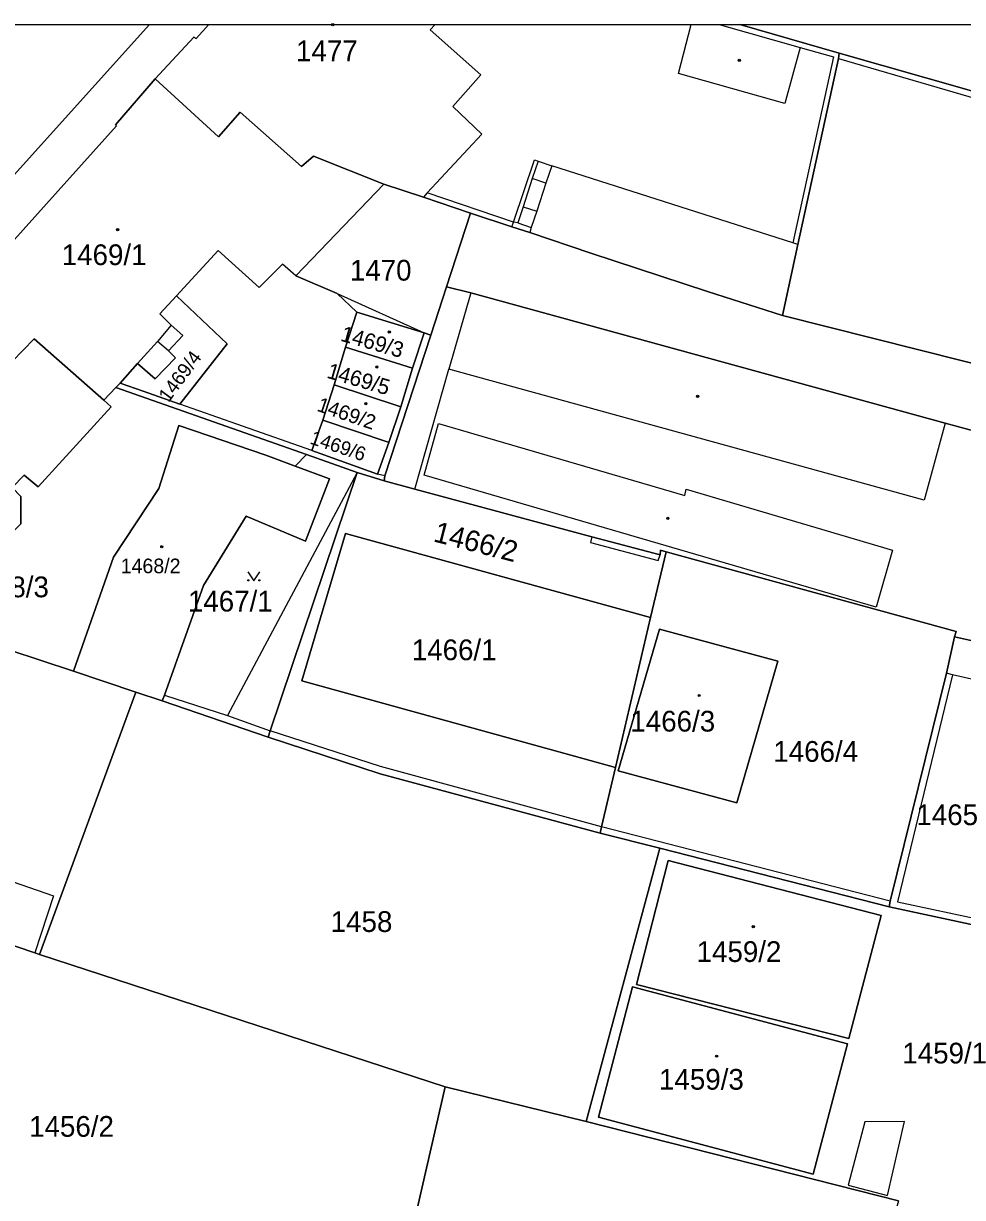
# Model space of a CAD drawing. Extents: x -598934 to -598196, y -1162208 to -1161502.
# Drawn here: x -598625.4 to -598548.4, y -1161601.3 to -1161505.1 of the extents above; entities that cross this region are included whole.
import ezdxf

# ---------------------------------------------------------------- set-up
doc = ezdxf.new("R2010")
doc.units = 0
for name, color, linetype in [('KN_CAR_KR', 7, 'Continuous'), ('KN_KULTURY', 7, 'Continuous'), ('KN_PARC_CIS_POZ', 7, 'Continuous'), ('KN_PARC_CIS_STAV', 7, 'Continuous'), ('KN_PARC_PLOCHA', 7, 'Continuous'), ('parcely_l', 7, 'Continuous')]:
    doc.layers.add(name, color=color, linetype=linetype)

msp = doc.modelspace()

# ---------------------------------------------------------------- linework, layer by layer
at = {"layer": 'KN_CAR_KR'}
for points in [[(-598694.17, -1161593.02), (-598615.083, -1161505.182)], [(-598591.66, -1161505.182), (-598592.05, -1161505.62)], [(-598571.7, -1161509.2), (-598570.648, -1161505.182)], [(-598568.365, -1161505.182), (-598561.73, -1161507.06)], [(-598592.05, -1161505.62), (-598587.9, -1161509.3)], [(-598561.73, -1161507.06), (-598562.98, -1161511.66)], [(-598561.73, -1161507.06), (-598558.98, -1161507.83)], [(-598558.98, -1161507.83), (-598562.33, -1161523.07)], [(-598558.58, -1161507.98), (-598547.24, -1161511.27)], [(-598587.9, -1161509.3), (-598590.2, -1161511.91)], [(-598562.98, -1161511.66), (-598571.7, -1161509.2)], [(-598590.2, -1161511.91), (-598587.83, -1161514.18)], [(-598587.83, -1161514.18), (-598592.31, -1161518.98)], [(-598585.24, -1161521.38), (-598583.51, -1161516.28)], [(-598583.2, -1161516.39), (-598583.69, -1161517.81)], [(-598583.51, -1161516.28), (-598583.2, -1161516.39)], [(-598583.2, -1161516.39), (-598582.07, -1161516.76)], [(-598582.07, -1161516.76), (-598582.58, -1161518.18)], [(-598562.33, -1161523.07), (-598582.07, -1161516.76)], [(-598583.69, -1161517.81), (-598584.43, -1161520.12)], [(-598582.58, -1161518.18), (-598583.69, -1161517.81)], [(-598592.31, -1161518.98), (-598592.61, -1161519.35)], [(-598585.24, -1161521.38), (-598592.31, -1161518.98)], [(-598582.58, -1161518.18), (-598583.32, -1161520.48)], [(-598584.43, -1161520.12), (-598584.87, -1161521.43)], [(-598584.43, -1161520.12), (-598583.32, -1161520.48)], [(-598583.32, -1161520.48), (-598583.77, -1161521.83)], [(-598585.35, -1161521.78), (-598585.24, -1161521.38)], [(-598584.87, -1161521.43), (-598585.24, -1161521.38)], [(-598584.87, -1161521.43), (-598583.77, -1161521.83)], [(-598583.77, -1161521.83), (-598583.88, -1161522.24)], [(-598609.45, -1161523.71), (-598612.85, -1161527.44)], [(-598606.09, -1161526.74), (-598609.45, -1161523.71)], [(-598561.9, -1161523.22), (-598562.33, -1161523.07)], [(-598604.16, -1161524.84), (-598606.09, -1161526.74)], [(-598603.09, -1161525.8), (-598604.16, -1161524.84)], [(-598599.7, -1161527.25), (-598592.55, -1161530.45)], [(-598588.73, -1161527.17), (-598590.52, -1161533.45)], [(-598613.31, -1161529.84), (-598614.42, -1161531.16)], [(-598614.42, -1161531.16), (-598616.06, -1161532.97)], [(-598613.52, -1161531.95), (-598614.42, -1161531.16)], [(-598593.31, -1161543.27), (-598590.52, -1161533.45)], [(-598551.54, -1161544.17), (-598590.52, -1161533.45)], [(-598617.49, -1161534.59), (-598617.85, -1161534.94)], [(-598607.91, -1161537.95), (-598612.58, -1161536.3)], [(-598601.77, -1161540.12), (-598607.91, -1161537.95)], [(-598592.55, -1161542.14), (-598591.39, -1161537.89)], [(-598591.39, -1161537.89), (-598571.18, -1161543.8)], [(-598549.82, -1161537.87), (-598551.54, -1161544.17)], [(-598598.04, -1161541.9), (-598608.67, -1161561.84)], [(-598595.79, -1161542.19), (-598596.38, -1161542.05)], [(-598555.5, -1161552.94), (-598592.55, -1161542.14)], [(-598571.18, -1161543.8), (-598571.06, -1161543.28)], [(-598571.06, -1161543.28), (-598554.16, -1161548.28)], [(-598578.81, -1161547.18), (-598578.9, -1161547.65)], [(-598578.9, -1161547.65), (-598573.36, -1161549.12)], [(-598573.36, -1161549.12), (-598573.21, -1161548.67)], [(-598554.16, -1161548.28), (-598555.5, -1161552.94)], [(-598549.22, -1161558.5), (-598549.73, -1161558.37)], [(-598549.22, -1161558.5), (-598553.73, -1161577.12)], [(-598545.5, -1161559.35), (-598549.22, -1161558.5)], [(-598613.84, -1161560.16), (-598608.67, -1161561.84)], [(-598608.67, -1161561.84), (-598605.18, -1161563.09)], [(-598596.12, -1161566.02), (-598605.18, -1161563.09)], [(-598578, -1161570.96), (-598596.12, -1161566.02)], [(-598639.77, -1161570.8), (-598622.94, -1161576.63)], [(-598554.34, -1161577.06), (-598578, -1161570.96)], [(-598622.94, -1161576.63), (-598624.47, -1161581.28)], [(-598553.73, -1161577.12), (-598539.35, -1161580.17)], [(-598556.42, -1161595.14), (-598557.79, -1161600.35)], [(-598553.17, -1161595.12), (-598556.42, -1161595.14)], [(-598554.56, -1161601.18), (-598553.17, -1161595.12)], [(-598557.79, -1161600.35), (-598554.56, -1161601.18)]]:
    msp.add_lwpolyline(points, dxfattribs=at)
at = {"layer": 'KN_KULTURY'}
msp.add_lwpolyline([(-598607.022, -1161550.052), (-598606.522, -1161550.802), (-598606.022, -1161550.052)], dxfattribs=at)
for centre, radius in [((-598600.05, -1161505.19), 0.09), ((-598600.05, -1161505.19), 0.0398), ((-598566.71, -1161508.12), 0.09), ((-598566.71, -1161508.12), 0.0398), ((-598617.69, -1161522.01), 0.09), ((-598617.69, -1161522.01), 0.0398), ((-598595.41, -1161530.39), 0.09), ((-598595.41, -1161530.39), 0.0398), ((-598596.43, -1161533.26), 0.09), ((-598596.43, -1161533.26), 0.0398), ((-598597.34, -1161536.27), 0.09), ((-598597.34, -1161536.27), 0.0398), ((-598570.13, -1161535.67), 0.09), ((-598570.13, -1161535.67), 0.0398), ((-598572.57, -1161545.67), 0.09), ((-598572.57, -1161545.67), 0.0398), ((-598614.07, -1161548), 0.09), ((-598614.07, -1161548), 0.0398), ((-598606.972, -1161550.751), 0.05), ((-598606.073, -1161550.751), 0.05), ((-598570, -1161560.19), 0.09), ((-598570, -1161560.19), 0.0398), ((-598565.56, -1161579.15), 0.09), ((-598565.56, -1161579.15), 0.0398), ((-598568.57, -1161589.76), 0.09), ((-598568.57, -1161589.76), 0.0398)]:
    msp.add_circle(centre, radius, dxfattribs=at)
at = {"layer": 'KN_PARC_PLOCHA'}
for points in [[(-598630.752, -1161505.182), (-598610.21, -1161505.182), (-598611.26, -1161506.34), (-598611.43, -1161506.21), (-598614.6, -1161509.64), (-598617.86, -1161513.42), (-598617.77, -1161513.49), (-598628.34, -1161525.22)], [(-598628.34, -1161525.22), (-598617.77, -1161513.49), (-598617.86, -1161513.42), (-598614.6, -1161509.64), (-598609.41, -1161514.39), (-598607.65, -1161512.38), (-598602.6, -1161516.83), (-598601.62, -1161515.98), (-598595.86, -1161518.27), (-598603.09, -1161525.8), (-598599.7, -1161527.25), (-598598.08, -1161528.78), (-598599.01, -1161531.64), (-598599.93, -1161534.73), (-598600.86, -1161537.61), (-598601.77, -1161540.12), (-598596.38, -1161542.05), (-598595.44, -1161539.45), (-598594.47, -1161536.53), (-598593.51, -1161533.35), (-598592.55, -1161530.45), (-598592, -1161530.65), (-598595.79, -1161542.19), (-598595.83, -1161542.6), (-598598.04, -1161541.9), (-598602.19, -1161540.44), (-598617.85, -1161534.94), (-598618.82, -1161535.97), (-598624.53, -1161530.96), (-598626.34, -1161532.82)], [(-598544.76, -1161539.24), (-598549.82, -1161537.87), (-598588.73, -1161527.17), (-598590.72, -1161526.69), (-598588.76, -1161520.66), (-598585.35, -1161521.78), (-598583.88, -1161522.24), (-598578.88, -1161523.94), (-598569.31, -1161527.06), (-598563.18, -1161529.03), (-598537.22, -1161535.57)], [(-598545.63, -1161556.15), (-598549.05, -1161555.39), (-598548.94, -1161554.94), (-598572.71, -1161548.42), (-598573.17, -1161548.28), (-598573.21, -1161548.67), (-598578.81, -1161547.18), (-598593.31, -1161543.27), (-598595.83, -1161542.6), (-598595.79, -1161542.19), (-598592, -1161530.65), (-598590.72, -1161526.69), (-598588.73, -1161527.17), (-598549.82, -1161537.87), (-598544.76, -1161539.24)], [(-598553.66, -1161601.61), (-598579.26, -1161595.13), (-598573.22, -1161572.72), (-598554.41, -1161577.51), (-598539.27, -1161580.77), (-598536.29, -1161581.38), (-598536, -1161581.45), (-598535.61, -1161581.53), (-598537.22, -1161589.72), (-598537.42, -1161590.8), (-598521.03, -1161593.46), (-598505.36, -1161596), (-598502.44, -1161596.49), (-598489.42, -1161598.43), (-598488.92, -1161595.52), (-598484.67, -1161596.22), (-598482.63, -1161596.62), (-598473.08, -1161597.8), (-598470.85, -1161599.65), (-598483.87, -1161615.19)]]:
    msp.add_lwpolyline(points, dxfattribs=at)
for points in [[(-598558.51, -1161507.54), (-598558.58, -1161507.98), (-598561.9, -1161523.22), (-598563.18, -1161529.03), (-598569.31, -1161527.06), (-598578.88, -1161523.94), (-598583.88, -1161522.24), (-598585.35, -1161521.78), (-598588.76, -1161520.66), (-598592.61, -1161519.35), (-598595.86, -1161518.27), (-598601.62, -1161515.98), (-598602.6, -1161516.83), (-598607.65, -1161512.38), (-598609.41, -1161514.39), (-598614.6, -1161509.64), (-598611.43, -1161506.21), (-598611.26, -1161506.34), (-598610.21, -1161505.182), (-598566.66, -1161505.182)], [(-598547.13, -1161510.79), (-598547.87, -1161510.57), (-598558.51, -1161507.54), (-598566.66, -1161505.182), (-598545.465, -1161505.182)], [(-598547.13, -1161510.79), (-598523.46, -1161516.17), (-598528.11, -1161537.69), (-598528.65, -1161537.6), (-598537.22, -1161535.57), (-598563.18, -1161529.03), (-598561.9, -1161523.22), (-598558.58, -1161507.98), (-598558.51, -1161507.54), (-598547.87, -1161510.57)], [(-598588.76, -1161520.66), (-598590.72, -1161526.69), (-598592, -1161530.65), (-598592.55, -1161530.45), (-598598.08, -1161528.78), (-598599.7, -1161527.25), (-598603.09, -1161525.8), (-598595.86, -1161518.27), (-598592.61, -1161519.35)], [(-598608.7, -1161531.35), (-598612.85, -1161527.44), (-598614.24, -1161528.91), (-598613.31, -1161529.84), (-598612.35, -1161530.67), (-598613.52, -1161531.95), (-598612.94, -1161532.5), (-598614.6, -1161534.24), (-598616.06, -1161532.97), (-598617.49, -1161534.59), (-598615.59, -1161535.24), (-598612.58, -1161536.3)], [(-598608.7, -1161531.35), (-598612.58, -1161536.3), (-598615.59, -1161535.24), (-598617.49, -1161534.59), (-598616.06, -1161532.97), (-598614.6, -1161534.24), (-598612.94, -1161532.5), (-598613.52, -1161531.95), (-598612.35, -1161530.67), (-598613.31, -1161529.84), (-598614.24, -1161528.91), (-598612.85, -1161527.44)], [(-598618.82, -1161535.97), (-598618.21, -1161536.53), (-598624.2, -1161543.08), (-598625.36, -1161542.13), (-598626.33, -1161543.15), (-598625.64, -1161543.87), (-598625.63, -1161546.11), (-598626.86, -1161547.35), (-598629.3, -1161547.65), (-598629.91, -1161547.09), (-598631.97, -1161549.09), (-598631.55, -1161549.59), (-598634.57, -1161552.93), (-598637.12, -1161551.82), (-598648.08, -1161546.91), (-598631.37, -1161528.39), (-598626.34, -1161532.82), (-598624.53, -1161530.96)], [(-598592.55, -1161530.45), (-598593.51, -1161533.35), (-598599.01, -1161531.64), (-598598.08, -1161528.78)], [(-598593.51, -1161533.35), (-598594.47, -1161536.53), (-598594.55, -1161536.5), (-598599.93, -1161534.73), (-598599.01, -1161531.64)], [(-598602.19, -1161540.44), (-598603.12, -1161541.39), (-598605.53, -1161540.5), (-598612.66, -1161538.05), (-598614.31, -1161543.23), (-598618.03, -1161548.84), (-598621.31, -1161558.21), (-598626.6, -1161556.44), (-598634.57, -1161552.93), (-598631.55, -1161549.59), (-598631.97, -1161549.09), (-598629.91, -1161547.09), (-598629.3, -1161547.65), (-598626.86, -1161547.35), (-598625.63, -1161546.11), (-598625.64, -1161543.87), (-598626.33, -1161543.15), (-598625.36, -1161542.13), (-598624.2, -1161543.08), (-598618.21, -1161536.53), (-598618.82, -1161535.97), (-598617.85, -1161534.94)], [(-598594.47, -1161536.53), (-598595.44, -1161539.45), (-598595.51, -1161539.43), (-598600.86, -1161537.61), (-598599.93, -1161534.73), (-598594.55, -1161536.5)], [(-598603.12, -1161541.39), (-598600.31, -1161542.44), (-598602.28, -1161547.55), (-598607.15, -1161545.5), (-598610.65, -1161551.18), (-598613.84, -1161560.16), (-598614.04, -1161560.64), (-598616.21, -1161559.92), (-598621.31, -1161558.21), (-598618.03, -1161548.84), (-598614.31, -1161543.23), (-598612.66, -1161538.05), (-598605.53, -1161540.5)], [(-598595.44, -1161539.45), (-598596.38, -1161542.05), (-598601.77, -1161540.12), (-598600.86, -1161537.61), (-598595.51, -1161539.43)], [(-598598.04, -1161541.9), (-598605.18, -1161563.09), (-598605.34, -1161563.6), (-598614.04, -1161560.64), (-598613.84, -1161560.16), (-598610.65, -1161551.18), (-598607.15, -1161545.5), (-598602.28, -1161547.55), (-598600.31, -1161542.44), (-598603.12, -1161541.39), (-598602.19, -1161540.44)], [(-598595.83, -1161542.6), (-598593.31, -1161543.27), (-598578.81, -1161547.18), (-598573.21, -1161548.67), (-598573.17, -1161548.28), (-598572.71, -1161548.42), (-598573.98, -1161553.79), (-598599, -1161546.9), (-598602.59, -1161559), (-598576.86, -1161566.09), (-598578, -1161570.96), (-598578.13, -1161571.48), (-598596.17, -1161566.61), (-598605.34, -1161563.6), (-598605.18, -1161563.09), (-598598.04, -1161541.9)], [(-598573.98, -1161553.79), (-598576.86, -1161566.09), (-598602.59, -1161559), (-598599, -1161546.9)], [(-598549.05, -1161555.39), (-598549.73, -1161558.37), (-598554.34, -1161577.06), (-598554.41, -1161577.51), (-598573.22, -1161572.72), (-598578.13, -1161571.48), (-598578, -1161570.96), (-598576.86, -1161566.09), (-598573.98, -1161553.79), (-598572.71, -1161548.42), (-598548.94, -1161554.94)], [(-598634.57, -1161552.93), (-598626.6, -1161556.44), (-598621.31, -1161558.21), (-598616.21, -1161559.92), (-598624.11, -1161581.44), (-598624.47, -1161581.28), (-598633.95, -1161578.1), (-598637.58, -1161576.44), (-598641.64, -1161574.59), (-598651.94, -1161570), (-598652.43, -1161569.8), (-598653.06, -1161569.51), (-598644.87, -1161560.47), (-598644.61, -1161560.16), (-598637.12, -1161551.82)], [(-598563.54, -1161557.38), (-598573.25, -1161554.76), (-598576.65, -1161566.36), (-598566.92, -1161568.98)], [(-598563.54, -1161557.38), (-598566.92, -1161568.98), (-598576.65, -1161566.36), (-598573.25, -1161554.76)], [(-598533.06, -1161559.15), (-598534.39, -1161565.06), (-598543.42, -1161563.26), (-598545.63, -1161573.35), (-598545.79, -1161574.1), (-598544.38, -1161574.35), (-598538.4, -1161575.55), (-598539.35, -1161580.17), (-598536.18, -1161580.86), (-598536.29, -1161581.38), (-598539.27, -1161580.77), (-598554.41, -1161577.51), (-598554.34, -1161577.06), (-598549.73, -1161558.37), (-598549.05, -1161555.39), (-598545.63, -1161556.15), (-598544.79, -1161556.37), (-598538.66, -1161557.82)], [(-598614.04, -1161560.64), (-598605.34, -1161563.6), (-598596.17, -1161566.61), (-598578.13, -1161571.48), (-598573.22, -1161572.72), (-598579.26, -1161595.13), (-598590.84, -1161592.28), (-598624.11, -1161581.44), (-598616.21, -1161559.92)], [(-598555.07, -1161578.24), (-598572.53, -1161573.73), (-598575.13, -1161583.88), (-598557.72, -1161588.3)], [(-598555.07, -1161578.24), (-598557.72, -1161588.3), (-598575.13, -1161583.88), (-598572.53, -1161573.73)], [(-598624.11, -1161581.44), (-598590.84, -1161592.28), (-598593.9, -1161605.62), (-598590.99, -1161606.41), (-598592.92, -1161615.58), (-598602.01, -1161612.53), (-598617.23, -1161607.95), (-598636.32, -1161601.91), (-598641.28, -1161599.7), (-598647.1, -1161597.16), (-598637.58, -1161576.44), (-598633.95, -1161578.1), (-598624.47, -1161581.28)], [(-598557.84, -1161588.74), (-598575.46, -1161584.07), (-598578.27, -1161594.76), (-598560.65, -1161599.43)], [(-598557.84, -1161588.74), (-598560.65, -1161599.43), (-598578.27, -1161594.76), (-598575.46, -1161584.07)], [(-598579.26, -1161595.13), (-598553.66, -1161601.61), (-598555.71, -1161608.8), (-598557.25, -1161608.48), (-598558.4, -1161613.55), (-598558.85, -1161616.58), (-598560.25, -1161623.59), (-598574.77, -1161620.33), (-598590.51, -1161616.21), (-598592.92, -1161615.58), (-598590.99, -1161606.41), (-598593.9, -1161605.62), (-598590.84, -1161592.28)]]:
    msp.add_lwpolyline(points, close=True, dxfattribs=at)
at = {"layer": 'parcely_l'}
for points in [[(-598630.752, -1161505.182), (-598610.21, -1161505.182)], [(-598614.6, -1161509.64), (-598611.43, -1161506.21), (-598611.26, -1161506.34), (-598610.21, -1161505.182)], [(-598610.21, -1161505.182), (-598566.66, -1161505.182)], [(-598558.51, -1161507.54), (-598566.66, -1161505.182)], [(-598566.66, -1161505.182), (-598545.465, -1161505.182)], [(-598558.51, -1161507.54), (-598558.58, -1161507.98), (-598561.9, -1161523.22), (-598563.18, -1161529.03)], [(-598547.13, -1161510.79), (-598547.87, -1161510.57), (-598558.51, -1161507.54)], [(-598614.6, -1161509.64), (-598617.86, -1161513.42), (-598617.77, -1161513.49), (-598628.34, -1161525.22), (-598628.59, -1161525.08), (-598631.37, -1161528.39)], [(-598595.86, -1161518.27), (-598601.62, -1161515.98), (-598602.6, -1161516.83), (-598607.65, -1161512.38), (-598609.41, -1161514.39), (-598614.6, -1161509.64)], [(-598598.08, -1161528.78), (-598599.7, -1161527.25), (-598603.09, -1161525.8), (-598595.86, -1161518.27)], [(-598595.86, -1161518.27), (-598592.61, -1161519.35), (-598588.76, -1161520.66)], [(-598588.76, -1161520.66), (-598590.72, -1161526.69)], [(-598563.18, -1161529.03), (-598569.31, -1161527.06), (-598578.88, -1161523.94), (-598583.88, -1161522.24), (-598585.35, -1161521.78), (-598588.76, -1161520.66)], [(-598590.72, -1161526.69), (-598592, -1161530.65)], [(-598590.72, -1161526.69), (-598588.73, -1161527.17), (-598549.82, -1161537.87), (-598544.76, -1161539.24), (-598545.04, -1161540.92), (-598542.48, -1161541.59), (-598544.38, -1161550.34), (-598537.46, -1161551.8), (-598516.82, -1161556.8), (-598495.04, -1161560.91), (-598494.82, -1161559.8), (-598493.1, -1161560.11), (-598492.97, -1161559.48), (-598484.76, -1161561.11), (-598485.07, -1161562.91), (-598482.22, -1161563.54), (-598481.91, -1161561.52), (-598475.6, -1161562.65), (-598475.88, -1161564.72), (-598476.73, -1161570.31)], [(-598608.7, -1161531.35), (-598612.58, -1161536.3), (-598615.59, -1161535.24), (-598617.49, -1161534.59), (-598616.06, -1161532.97), (-598614.6, -1161534.24), (-598612.94, -1161532.5), (-598613.52, -1161531.95), (-598612.35, -1161530.67), (-598613.31, -1161529.84), (-598614.24, -1161528.91), (-598612.85, -1161527.44), (-598608.7, -1161531.35)], [(-598631.37, -1161528.39), (-598626.34, -1161532.82), (-598624.53, -1161530.96), (-598618.82, -1161535.97)], [(-598599.01, -1161531.64), (-598598.08, -1161528.78)], [(-598592.55, -1161530.45), (-598598.08, -1161528.78)], [(-598563.18, -1161529.03), (-598537.22, -1161535.57)], [(-598592.55, -1161530.45), (-598593.51, -1161533.35)], [(-598592, -1161530.65), (-598592.55, -1161530.45)], [(-598595.83, -1161542.6), (-598595.79, -1161542.19), (-598592, -1161530.65)], [(-598599.93, -1161534.73), (-598599.01, -1161531.64)], [(-598599.01, -1161531.64), (-598593.51, -1161533.35)], [(-598593.51, -1161533.35), (-598594.47, -1161536.53)], [(-598618.82, -1161535.97), (-598617.85, -1161534.94), (-598602.19, -1161540.44)], [(-598599.93, -1161534.73), (-598600.86, -1161537.61)], [(-598594.47, -1161536.53), (-598594.55, -1161536.5), (-598599.93, -1161534.73)], [(-598618.82, -1161535.97), (-598618.21, -1161536.53), (-598624.2, -1161543.08), (-598625.36, -1161542.13), (-598626.33, -1161543.15), (-598625.64, -1161543.87), (-598625.63, -1161546.11), (-598626.86, -1161547.35), (-598629.3, -1161547.65), (-598629.91, -1161547.09), (-598631.97, -1161549.09), (-598631.55, -1161549.59), (-598634.57, -1161552.93)], [(-598595.44, -1161539.45), (-598594.47, -1161536.53)], [(-598603.12, -1161541.39), (-598605.53, -1161540.5), (-598612.66, -1161538.05), (-598614.31, -1161543.23), (-598618.03, -1161548.84), (-598621.31, -1161558.21)], [(-598595.44, -1161539.45), (-598596.38, -1161542.05), (-598601.77, -1161540.12), (-598600.86, -1161537.61)], [(-598600.86, -1161537.61), (-598595.51, -1161539.43), (-598595.44, -1161539.45)], [(-598602.19, -1161540.44), (-598603.12, -1161541.39)], [(-598598.04, -1161541.9), (-598602.19, -1161540.44)], [(-598614.04, -1161560.64), (-598613.84, -1161560.16), (-598610.65, -1161551.18), (-598607.15, -1161545.5), (-598602.28, -1161547.55), (-598600.31, -1161542.44), (-598603.12, -1161541.39)], [(-598605.34, -1161563.6), (-598605.18, -1161563.09), (-598598.04, -1161541.9)], [(-598598.04, -1161541.9), (-598595.83, -1161542.6)], [(-598595.83, -1161542.6), (-598593.31, -1161543.27), (-598578.81, -1161547.18), (-598573.21, -1161548.67), (-598573.17, -1161548.28), (-598572.71, -1161548.42)], [(-598576.86, -1161566.09), (-598602.59, -1161559), (-598599, -1161546.9), (-598573.98, -1161553.79)], [(-598572.71, -1161548.42), (-598573.98, -1161553.79)], [(-598549.05, -1161555.39), (-598548.94, -1161554.94), (-598572.71, -1161548.42)], [(-598621.31, -1161558.21), (-598626.6, -1161556.44), (-598634.57, -1161552.93)], [(-598573.98, -1161553.79), (-598576.86, -1161566.09)], [(-598563.54, -1161557.38), (-598566.92, -1161568.98), (-598576.65, -1161566.36), (-598573.25, -1161554.76), (-598563.54, -1161557.38)], [(-598554.41, -1161577.51), (-598554.34, -1161577.06), (-598549.73, -1161558.37), (-598549.05, -1161555.39)], [(-598549.05, -1161555.39), (-598545.63, -1161556.15), (-598544.79, -1161556.37), (-598538.66, -1161557.82), (-598533.06, -1161559.15)], [(-598621.31, -1161558.21), (-598616.21, -1161559.92)], [(-598624.11, -1161581.44), (-598616.21, -1161559.92)], [(-598616.21, -1161559.92), (-598614.04, -1161560.64)], [(-598614.04, -1161560.64), (-598605.34, -1161563.6)], [(-598578.13, -1161571.48), (-598596.17, -1161566.61), (-598605.34, -1161563.6)], [(-598576.86, -1161566.09), (-598578, -1161570.96), (-598578.13, -1161571.48)], [(-598578.13, -1161571.48), (-598573.22, -1161572.72)], [(-598573.22, -1161572.72), (-598579.26, -1161595.13)], [(-598554.41, -1161577.51), (-598573.22, -1161572.72)], [(-598555.07, -1161578.24), (-598557.72, -1161588.3), (-598575.13, -1161583.88), (-598572.53, -1161573.73), (-598555.07, -1161578.24)], [(-598637.58, -1161576.44), (-598633.95, -1161578.1), (-598624.47, -1161581.28), (-598624.11, -1161581.44)], [(-598536.29, -1161581.38), (-598539.27, -1161580.77), (-598554.41, -1161577.51)], [(-598624.11, -1161581.44), (-598590.84, -1161592.28)], [(-598557.84, -1161588.74), (-598560.65, -1161599.43), (-598578.27, -1161594.76), (-598575.46, -1161584.07), (-598557.84, -1161588.74)], [(-598590.84, -1161592.28), (-598593.9, -1161605.62), (-598590.99, -1161606.41), (-598592.92, -1161615.58)], [(-598579.26, -1161595.13), (-598590.84, -1161592.28)], [(-598579.26, -1161595.13), (-598553.66, -1161601.61)]]:
    msp.add_lwpolyline(points, dxfattribs=at)

# ---------------------------------------------------------------- texts
at = {"layer": 'KN_PARC_CIS_POZ'}
for s, p in [('1470', (-598598.647, -1161526.18)), ('1467/1', (-598611.927, -1161553.31)), ('1466/1', (-598593.567, -1161557.3)), ('1465', (-598552.187, -1161570.82)), ('1458', (-598600.217, -1161579.58))]:
    msp.add_text(s, height=1.7, dxfattribs=at).set_placement(p)
for s, height, rotation, p in [('1469/4', 1.14, 53.48929, (-598613.512, -1161536.226)), ('1469/6', 1.14, 341.58094, (-598601.994, -1161539.529)), ('1466/2', 1.7, 345.60027, (-598591.875, -1161547.546))]:
    msp.add_text(s, height=height, rotation=rotation, dxfattribs=at).set_placement(p)
at = {"layer": 'KN_PARC_CIS_STAV'}
for s, height, p in [('1477', 1.7, (-598603.062, -1161508.19)), ('1469/1', 1.7, (-598622.272, -1161524.91)), ('1468/2', 1.2, (-598617.44, -1161550.17)), ('1468/3', 1.7, (-598630.282, -1161552.14)), ('1466/3', 1.7, (-598575.642, -1161563.15)), ('1466/4', 1.7, (-598563.922, -1161565.63)), ('1459/2', 1.7, (-598570.212, -1161582.04)), ('1459/1', 1.7, (-598553.342, -1161590.36)), ('1459/3', 1.7, (-598573.292, -1161592.51)), ('1456/2', 1.7, (-598624.947, -1161596.37))]:
    msp.add_text(s, height=height, dxfattribs=at).set_placement(p)
for s, height, rotation, p in [('1469/3', 1.28, 344.11223, (-598599.488, -1161531.097)), ('1469/5', 1.28, 343.83536, (-598600.613, -1161534.13)), ('1469/2', 1.2, 341.09958, (-598601.42, -1161536.839))]:
    msp.add_text(s, height=height, rotation=rotation, dxfattribs=at).set_placement(p)

doc.saveas('drawing.dxf')
